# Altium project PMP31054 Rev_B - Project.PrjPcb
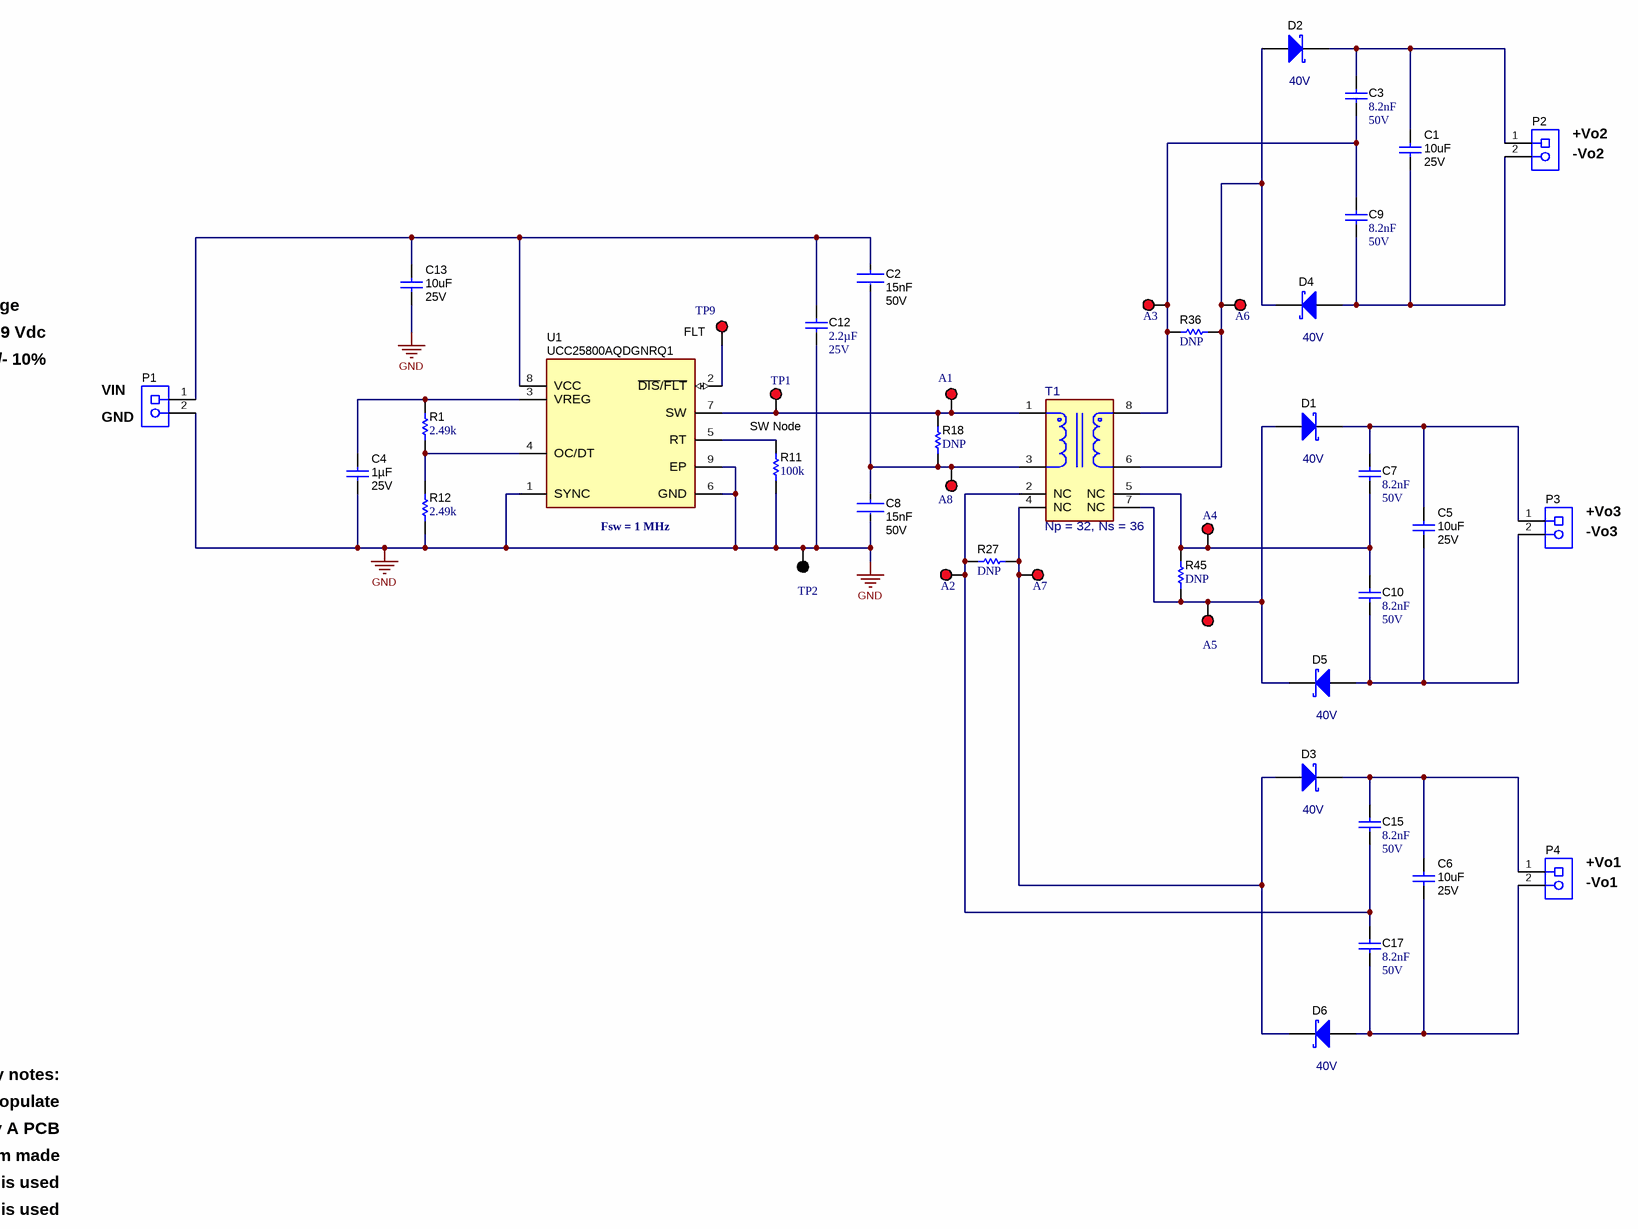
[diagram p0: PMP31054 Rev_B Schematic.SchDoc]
CopyrightYear: 2021; PCB_Layout: S.Panaro; PCB_Rev: A; PRJ_Customer: Public Release; PRJ_Engineer: S.Panaro R.Scibilia; PRJ_Number: PMP31054; PRJ_Title: 1.5W 3-output Isolated LLC Converter; SCH_Rev: B; TechSupport: http://www.ti.com/support; TID: N/A
2 sheets, 74 parts. Net scope: global (net labels, ports and power ports of the same name join across sheets).
Board file: PMP31054 Rev_B - PCB.PcbDoc
Sheets:
  PMP31054 Rev_B Schematic.SchDoc
  PMP31054 Rev_B - hardware.SchDoc

## Sheet PMP31054 Rev_B Schematic.SchDoc: 1.5W 3-output Isolated LLC Converter
size 431 x 279 mm; Date: Not shown in title block; ApprovedBy: Not shown in title block; CheckedBy: Not shown in title block; Author: Not shown in title block; CompanyName: Not shown in title block; DrawnBy: S.Panaro R.Scibilia; Engineer: Not shown in title block; Organization: Not shown in title block; Address1: Not shown in title block; Address2: Not shown in title block; Address3: Not shown in title block; Address4: Not shown in title block; DocumentNumber: 1; Revision: Use project parameter SCH_Rev; SheetNumber: 1; SheetTotal: 1; PageSetup: Record=PageOptions¦CenterHorizontal=True¦CenterVertical=True¦PrintScale=1.00¦XCorrection=1.00¦YCorrection=1.00¦PrintKind=0¦BorderSize=5000000¦LeftOffset=0¦BottomOffset=0¦Orientation=2¦PaperLength=1000¦PaperWidth=1000¦Scale=100¦PaperSource=15¦PrintQuality=600¦MediaType=1¦DitherType=10¦PaperKind=Letter¦PrintScaleMode=1

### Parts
A1  5010  [Keystone5010]  (value not drawn)
A2  5010  [Keystone5010]  (value not drawn)
A3  5010  [Keystone5010]  (value not drawn)
A4  5010  [Keystone5010]  (value not drawn)
A5  5010  [Keystone5010]  (value not drawn)
A6  5010  [Keystone5010]  (value not drawn)
A7  5010  [Keystone5010]  (value not drawn)
A8  5010  [Keystone5010]  (value not drawn)
C1  VDC_V: 25V  ValueDisplayed: 10uF  [1206]  (hidden comment: 885012208069)
C2  Cap_F: 15nF  VDC_V: 50V  [FP-885012206090_0603-MFG]  (hidden comment: 885012206090)
C3  Cap_F: 8.2nF  VDC_V: 50V  [0603]  (hidden comment: CL10B822KB8NNNC)
C4  Cap_F: 1µF  VDC_V: 25V  [0603]  (hidden comment: 885012206076)
C5  VDC_V: 25V  ValueDisplayed: 10uF  [1206]  (hidden comment: 885012208069)
C6  VDC_V: 25V  ValueDisplayed: 10uF  [1206]  (hidden comment: 885012208069)
C7  Cap_F: 8.2nF  VDC_V: 50V  [0603]  (hidden comment: CL10B822KB8NNNC)
C8  Cap_F: 15nF  VDC_V: 50V  [FP-885012206090_0603-MFG]  (hidden comment: 885012206090)
C9  Cap_F: 8.2nF  VDC_V: 50V  [0603]  (hidden comment: CL10B822KB8NNNC)
C10  Cap_F: 8.2nF  VDC_V: 50V  [0603]  (hidden comment: CL10B822KB8NNNC)
C12  Cap_F: 2.2µF  VDC_V: 25V  [0805_HV]  (hidden comment: 885012207079)
C13  VDC_V: 25V  ValueDisplayed: 10uF  [1210_220]  (hidden comment: 885012209028)
C15  Cap_F: 8.2nF  VDC_V: 50V  [0603]  (hidden comment: CL10B822KB8NNNC)
C17  Cap_F: 8.2nF  VDC_V: 50V  [0603]  (hidden comment: CL10B822KB8NNNC)
D1  value 40V  [SMA]  (hidden comment: CMSH1-40M TR13)
D2  value 40V  [SMA]  (hidden comment: CMSH1-40M TR13)
D3  value 40V  [SMA]  (hidden comment: CMSH1-40M TR13)
D4  value 40V  [SMA]  (hidden comment: CMSH1-40M TR13)
D5  value 40V  [SMA]  (hidden comment: CMSH1-40M TR13)
D6  value 40V  [SMA]  (hidden comment: CMSH1-40M TR13)
P1  691214110002  [Wurth_691214110002]  (value not drawn)
P2  691214110002  [Wurth_691214110002]  (value not drawn)
P3  691214110002  [Wurth_691214110002]  (value not drawn)
P4  691214110002  [Wurth_691214110002]  (value not drawn)
R1  ValueDisplayed: 2.49k  [0603]  (hidden comment: CRCW06032K49FKEA)
R11  ValueDisplayed: 100k  [0603]  (hidden comment: CRCW0603100KFKEA)
R12  ValueDisplayed: 2.49k  [0603]  (hidden comment: CRCW06032K49FKEA)
R18  DNP  [0402]
R27  DNP  [0402]
R36  DNP  [0402]
R45  DNP  [0402]
T1  Np = 32, Ns = 36  [FP-750319177r02_SMT_11MM21_11MM3-MFG]
TP1  5010  [Keystone5010]  (value not drawn)
TP2  5011  [Keystone5011]  (value not drawn)
TP9  5010  [Keystone5010]  (value not drawn)
U1  UCC25800AQDGNRQ1  [DGN0008G-MFG]

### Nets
GND: C4.2 C8.2 C12.2 C13.2 P1.2 R11.1 R12.1 TP2.1 U1.1(SYNC) U1.6(GND) U1.9(EP)
NetA1_1: A1.1 R18.2 T1.1 TP1.1 U1.7(SW)
NetA2_1: A2.1 C15.2 C17.1 R27.2 T1.2(NC)
NetA3_1: A3.1 C3.2 C9.1 R36.2 T1.8
NetA4_1: A4.1 C7.2 C10.1 R45.2 T1.5(NC)
NetA5_1: A5.1 D1.2(A) D5.1(K) R45.1 T1.7(NC)
NetA6_1: A6.1 D2.2(A) D4.1(K) R36.1 T1.6
NetA7_1: A7.1 D3.2(A) D6.1(K) R27.1 T1.4(NC)
NetA8_1: A8.1 C2.2 C8.1 R18.1 T1.3
NetC1_1: C1.1 C3.1 D2.1(K) P2.1
NetC1_2: C1.2 C9.2 D4.2(A) P2.2
NetC2_1: C2.1 C12.1 C13.1 P1.1 U1.8(VCC)
NetC4_1: C4.1 R1.2 U1.3(VREG)
NetC5_1: C5.1 C7.1 D1.1(K) P3.1
NetC5_2: C5.2 C10.2 D5.2(A) P3.2
NetC6_1: C6.1 C15.1 D3.1(K) P4.1
NetC6_2: C6.2 C17.2 D6.2(A) P4.2
NetR1_1: R1.1 R12.2 U1.4(OC/DT)
NetR11_2: R11.2 U1.5(RT)
NetTP9_1: TP9.1 U1.2(~{DIS}/~{FLT})

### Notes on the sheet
- (near P2) +Vo2
- (near P2) -Vo2
- Input Voltage
- 9 Vdc
- (near TP9) FLT
- +/- 10%
- (near P1) VIN
- (near P1) GND
- SW Node
- (near U1) Fsw = 1 MHz
- (near P3) +Vo3
- (near P3) -Vo3
- (near P4) +Vo1
- (near P4) -Vo1
- Assembly notes:
- Built on PMP31054 Rev A PCB
- "DNP" = do not populate
- Transformer T1 is custom made
- Place zero Ohm resistors on R18, R27, R45 and R36 if the printed coils is used
- Do not populate R18, R27, R45 and R36 if the transformer T1 is used

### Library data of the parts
A1-A8 TP1 TP9 = CMP-0055147-1: Test Point, Multipurpose, Red, TH; Manufacturer: Keystone; CNHeader: FALSE; Green_Lifecycle: Active; Green_REACh: Passed; ContactFinish: Silver; CT: TRUE
C1 C5 C6 = CMP-0008574-2: CAP, CERM, 10 uF, 25 V, +/- 10%, X7R, 1206; Manufacturer: Wurth Elektronik; TaMin_C: -55°C; Polarized: N; SizeAreaWB_mm2: 10.92; Value1: Unknown; U/M: EA; Value: 10uF; TaMax_C: 125°C; SizeZ_mm: 1.35; SizeX_mm: 3.2; SizeY_mm: 1.6; SizeArea_mm2: 5.12; Cap_F: 10µF; AEC Category: Q200
C2 C8 = CMP-0087155-1: CAP CER 0.015UF 50V X7R 0603; Manufacturer: Wurth Electronics; TempCo: 15%; SizeZ_mm: 0.95mm; Tolerance_%: 10%; AEC Qualified: No; Symbol Name: SYM-885012206090
C3 C7 C9 C10 C15 C17 = CMP-0860998-1: CAP, CERM, 8200 pF, 50 V,+/- 10%, X7R, 0603; Manufacturer: Samsung Electro-Mechanics; SizeArea_mm2: 1.28; TaMax_C: 125°C; AEC Qualified: N; AEC Category: Q200; SizeAreaWB_mm2: 4.68; ValueDisplayed: 8200pF; SizeY_mm: 0.8; SizeX_mm: 1.6; SizeZ_mm: 1; Value: 8200pF; TaMin_C: -55°C; U/M: EA
C4 = CMP-0006833-4: CAP, CERM, 1 uF, 25 V, +/- 10%, X7R, 0603; Manufacturer: Wurth Elektronik; TaMin_C: -55°C; Polarized: N; SizeAreaWB_mm2: 4.68; Value1: Unknown; U/M: EA; Value: 1uF; TaMax_C: 125°C; SizeZ_mm: 1; SizeX_mm: 1.6; SizeY_mm: 0.8; SizeArea_mm2: 1.28; AEC Category: Q200
C12 = CMP-0007977-1: CAP, CERM, 2.2 uF, 25 V, +/- 10%, X7R, 0805; Manufacturer: Wuerth; TaMin_C: -55°C; Polarized: N; SizeAreaWB_mm2: 6.75; U/M: EA; Value: 2.2uF; TaMax_C: 125°C; SizeZ_mm: 1.45; SizeX_mm: 2; SizeY_mm: 1.25; Cap_Case: 0805; SizeArea_mm2: 2.5; AEC Qualified: Y; AEC Grade: 1
C13 = CMP-0064938-2: CAP, CERM, 10 uF, 25 V,+/- 10%, X7R, 1210; Manufacturer: Wurth Elektronik; TaMin_C: -55°C; Polarized: N; SizeAreaWB_mm2: 14.7; Value1: Unknown; U/M: EA; Value: 10uF; TaMax_C: 125°C; SizeZ_mm: 2.2; SizeX_mm: 3.2; SizeY_mm: 2.5; Cap_Case: 1210; SizeArea_mm2: 8; Cap_F: 10µF; AEC Category: Q200
D1-D6 = CMP-0028785-1: Diode Schottky 40V 1A Surface Mount SMA; Manufacturer: Diodes Inc.; Io_A: 3A; Green_Lifecycle: Not Set; SizeAreaWB_mm2: 37.3428; Green_REACh: Incomplete; TJmax_C: 150°C; U/M: EA; SizeZ_mm: 2.87; SizeX_mm: 5.59; SizeY_mm: 2.92; Vf_V: 700mV; Value2: 0.7V; SizeArea_mm2: 16.3228; AEC Qualified: Y; AEC Category: Q101
P1-P4 = CMP-0054825-2: Terminal Block, 3.5mm, 2x1, Tin, TH; Manufacturer: Wurth Elektronik; Pitch_mm: 3.5; CT: TRUE; CNHeader: FALSE; Voltage_V: 300V; Gender: Female; Cert_UL: Y; Row_Count: 1; Current_A: 10A
R1 R12 = CMP-0022277-4: RES, 2.49 k, 1%, 0.1 W, AEC-Q200 Grade 0, 0603; Manufacturer: Vishay-Dale; Power_W: 100mW; TempCo: 100 ppm/C; Value_Code: 2k49; Value: 2.49k; EIA_Code: E96; SizeX_mm: 1.6; SizeY_mm: 0.8; SizeZ_mm: 1; Value2: 0.1W; SizeArea_mm2: 1.28; AEC Qualified: Y; VDC_V: 75V; AEC Category: Q200; AEC Grade: 0
R11 = CMP-0021990-4: RES, 100 k, 1%, 0.1 W, AEC-Q200 Grade 0, 0603; Manufacturer: Vishay-Dale; Power_W: 100mW; TempCo: 100 ppm/C; Value: 100k; EIA_Code: E96; SizeX_mm: 1.6; SizeY_mm: 0.8; SizeZ_mm: 1; Value2: 0.1W; SizeArea_mm2: 1.28; AEC Qualified: Y; VDC_V: 75V; AEC Category: Q200; AEC Grade: 0
R18 R27 R36 R45 = CMP-0078660-1: Power_W: 250mW; TempCo: 300 ppm/C; Value1: 1%; EIA_Code: E96; Res_ohm: 0.1; SizeX_mm: 1; SizeY_mm: 0.5; SizeZ_mm: 0.6; Value2: 0.25W; AEC Qualified: N; AEC Category: Q200
T1 = CMP-0091345-1: Transformer, coreless EFD20, custom; AEC Qualified: No; Ns1toNp: 1:1.12; Rsec1_ohm: 0.122; Ind_H: 5.9µH; Frequency_Fixed: 1MHz; SizeZ_mm: 12.2mm
TP2 = CMP-0055148-1: Test Point, Multipurpose, Black, TH; Manufacturer: Keystone; CNHeader: FALSE; Green_Lifecycle: Active; Green_REACh: Passed; ContactFinish: Silver; CT: TRUE
U1 = CMP-0088494-2: Open Loop LLC Transformer Driver for Isolated Bias Supplies; Manufacturer: Texas Instruments; Min Supply Voltage: 12V; SizeZ_mm: 1.1mm; Number Of Outputs: 1; Standoff Height: 0.05mm; AEC Category: Q200; Max Duty Cycle: 50%; TaMin_C: -40°C; TJmax_C: +150°C; AEC Qualified: No; Switching Frequency: 100-2000kHz; CompType: IC; Max Supply Voltage: 36V; TaMax_C: +125°C; Output Type: Other; Nominal Supply Current: 500uA

## Sheet PMP31054 Rev_B - hardware.SchDoc: Details of the hardware components
size 431 x 279 mm; Date: Not shown in title block; ApprovedBy: Not shown in title block; CheckedBy: Not shown in title block; Author: Not shown in title block; CompanyName: Not shown in title block; DrawnBy: S.Panaro R.Scibilia; Engineer: Not shown in title block; Organization: Not shown in title block; Address1: Not shown in title block; Address2: Not shown in title block; Address3: Not shown in title block; Address4: Not shown in title block; DocumentNumber: 1; Revision: Use project parameter SCH_Rev; SheetNumber: 3; SheetTotal: 3; PageSetup: Record=PageOptions¦CenterHorizontal=True¦CenterVertical=True¦PrintScale=1.00¦XCorrection=1.00¦YCorrection=1.00¦PrintKind=0¦BorderSize=5000000¦LeftOffset=0¦BottomOffset=0¦Orientation=2¦PaperLength=1000¦PaperWidth=1000¦Scale=100¦PaperSource=15¦PrintQuality=600¦MediaType=1¦DitherType=10¦PaperKind=Letter¦PrintScaleMode=1
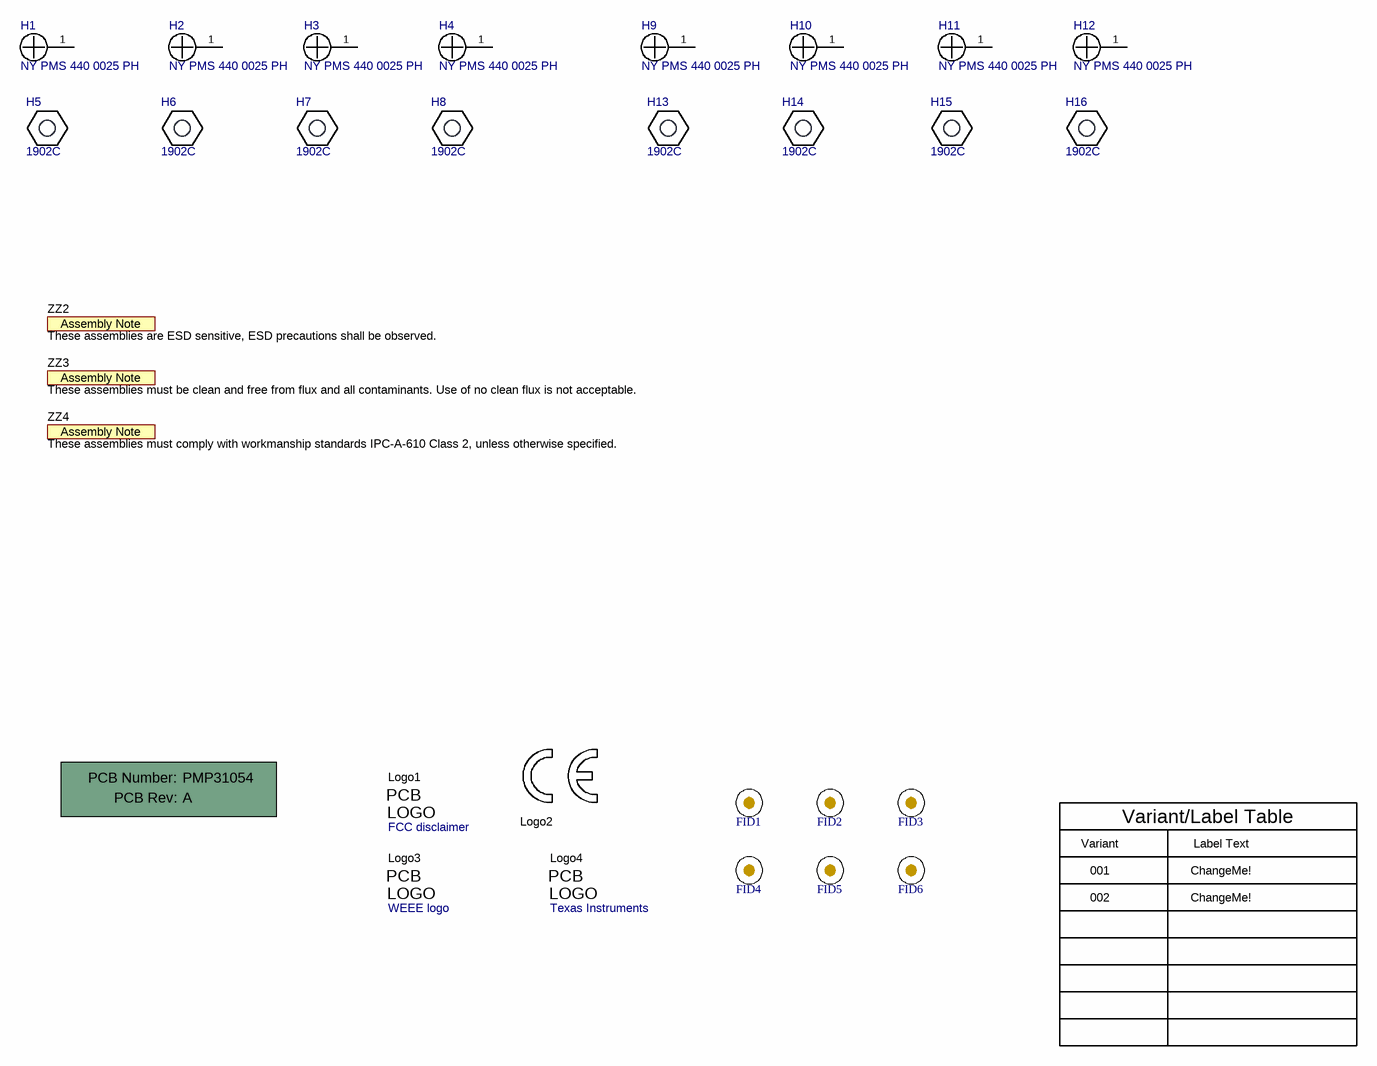
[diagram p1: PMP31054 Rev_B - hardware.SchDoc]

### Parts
!PCB?  Printed Circuit Board  (value not drawn)  (mechanical)
FID1  Fiducial  [Fiducial6.4-20]  (value not drawn)
FID2  Fiducial  [Fiducial6.4-20]  (value not drawn)
FID3  Fiducial  [Fiducial6.4-20]  (value not drawn)
FID4  Fiducial  [Fiducial6.4-20]  (value not drawn)
FID5  Fiducial  [Fiducial6.4-20]  (value not drawn)
FID6  Fiducial  [Fiducial6.4-20]  (value not drawn)
H1  NY PMS 440 0025 PH  [NY PMS 440 0025 PH]
H2  NY PMS 440 0025 PH  [NY PMS 440 0025 PH]
H3  NY PMS 440 0025 PH  [NY PMS 440 0025 PH]
H4  NY PMS 440 0025 PH  [NY PMS 440 0025 PH]
H5  1902C  [Keystone_1902C]
H6  1902C  [Keystone_1902C]
H7  1902C  [Keystone_1902C]
H8  1902C  [Keystone_1902C]
H9  NY PMS 440 0025 PH  [NY PMS 440 0025 PH]
H10  NY PMS 440 0025 PH  [NY PMS 440 0025 PH]
H11  NY PMS 440 0025 PH  [NY PMS 440 0025 PH]
H12  NY PMS 440 0025 PH  [NY PMS 440 0025 PH]
H13  1902C  [Keystone_1902C]
H14  1902C  [Keystone_1902C]
H15  1902C  [Keystone_1902C]
H16  1902C  [Keystone_1902C]
Logo1  FCC disclaimer  [FCC_disclaimer]  (no BOM)
Logo2  CE Mark  [CE_Mark_5mm]  (value not drawn)  (no BOM)
Logo3  WEEE logo  [WEEE_Minimum]  (no BOM)
Logo4  Texas Instruments  [TI_Horizontal_Overlay_Medium]  (no BOM)
ZZ2  These assemblies are ESD sensitive, ESD precautions shall be observed.  [AssemblyNote]  (no BOM)
ZZ3  These assemblies must be clean and free from flux and all contaminants. Use of no clean flux is not acceptable.  [AssemblyNote]  (no BOM)
ZZ4  These assemblies must comply with workmanship standards IPC-A-610 Class 2, unless otherwise specified.  [AssemblyNote]  (no BOM)

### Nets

Not connected (* = marked no-connect by the designer): H1 1; H2 1; H3 1; H4 1; H9 1; H10 1; H11 1; H12 1

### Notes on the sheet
- Variant/Label Table
- Variant
- 001
- 002
- Label Text
- ChangeMe!

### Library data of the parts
!PCB? = PCB: Manufacturer: Any; PartNumber: PMP31054; SymbolCreator: a0412235
FID1-FID6 = CMP-0077181-1: Fiducial mark.  There is nothing to buy or mount.
H1-H4 H9-H12 = CMP-0003617-1: Machine Screw, Round, #4-40 x 1/4, Nylon, Philips panhead; Manufacturer: B&F Fastener Supply; CompType: Hardware
H5-H8 H13-H16 = CMP-0003610-1: Standoff, Hex, 0.5"L #4-40 Nylon; Manufacturer: Keystone; CompType: Hardware
Logo1 = CMP-0074847-1: FCC_disclaimer
Logo2 = CMP-0074844-1: SymbolCreator: a0412235
Logo3 = CMP-0074769-1
Logo4 = CMP-0074838-1: Texas Instrument Corporate Signature; SymbolCreator: a0412235; Lib Reference: TI_Logo
ZZ2 = CMP-0077236-1
ZZ3 = CMP-0077237-1
ZZ4 = CMP-0077238-1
